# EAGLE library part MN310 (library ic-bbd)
Clock Driver for BBD
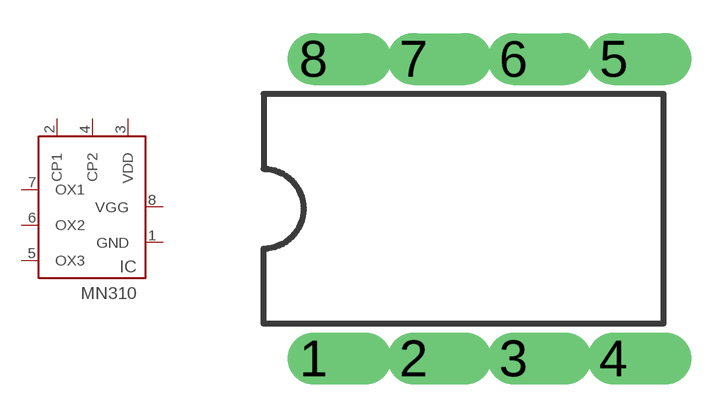
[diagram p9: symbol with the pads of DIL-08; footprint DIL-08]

Designator prefix IC

## MN3101  [DIL-08]
1  GND
2  CP1
3  VDD
4  CP2
5  OX3
6  OX2
7  OX1
8  VGG

## MN3102  [DIL-08]
1  VDD
2  CP1
3  GND
4  CP2
5  OX3
6  OX2
7  OX1
8  VGG

## MN3105  [DIL-08]
Pads as for DIL-08

## Footprint DIL-08 (pad centres in mm)
Dual In Line Package
drill 0.813 offset: 1 -3.81,-3.81; 2 -1.27,-3.81; 3 1.27,-3.81; 4 3.81,-3.81; 5 3.81,3.81; 6 1.27,3.81; 7 -1.27,3.81; 8 -3.81,3.81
